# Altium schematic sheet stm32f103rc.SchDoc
size A4
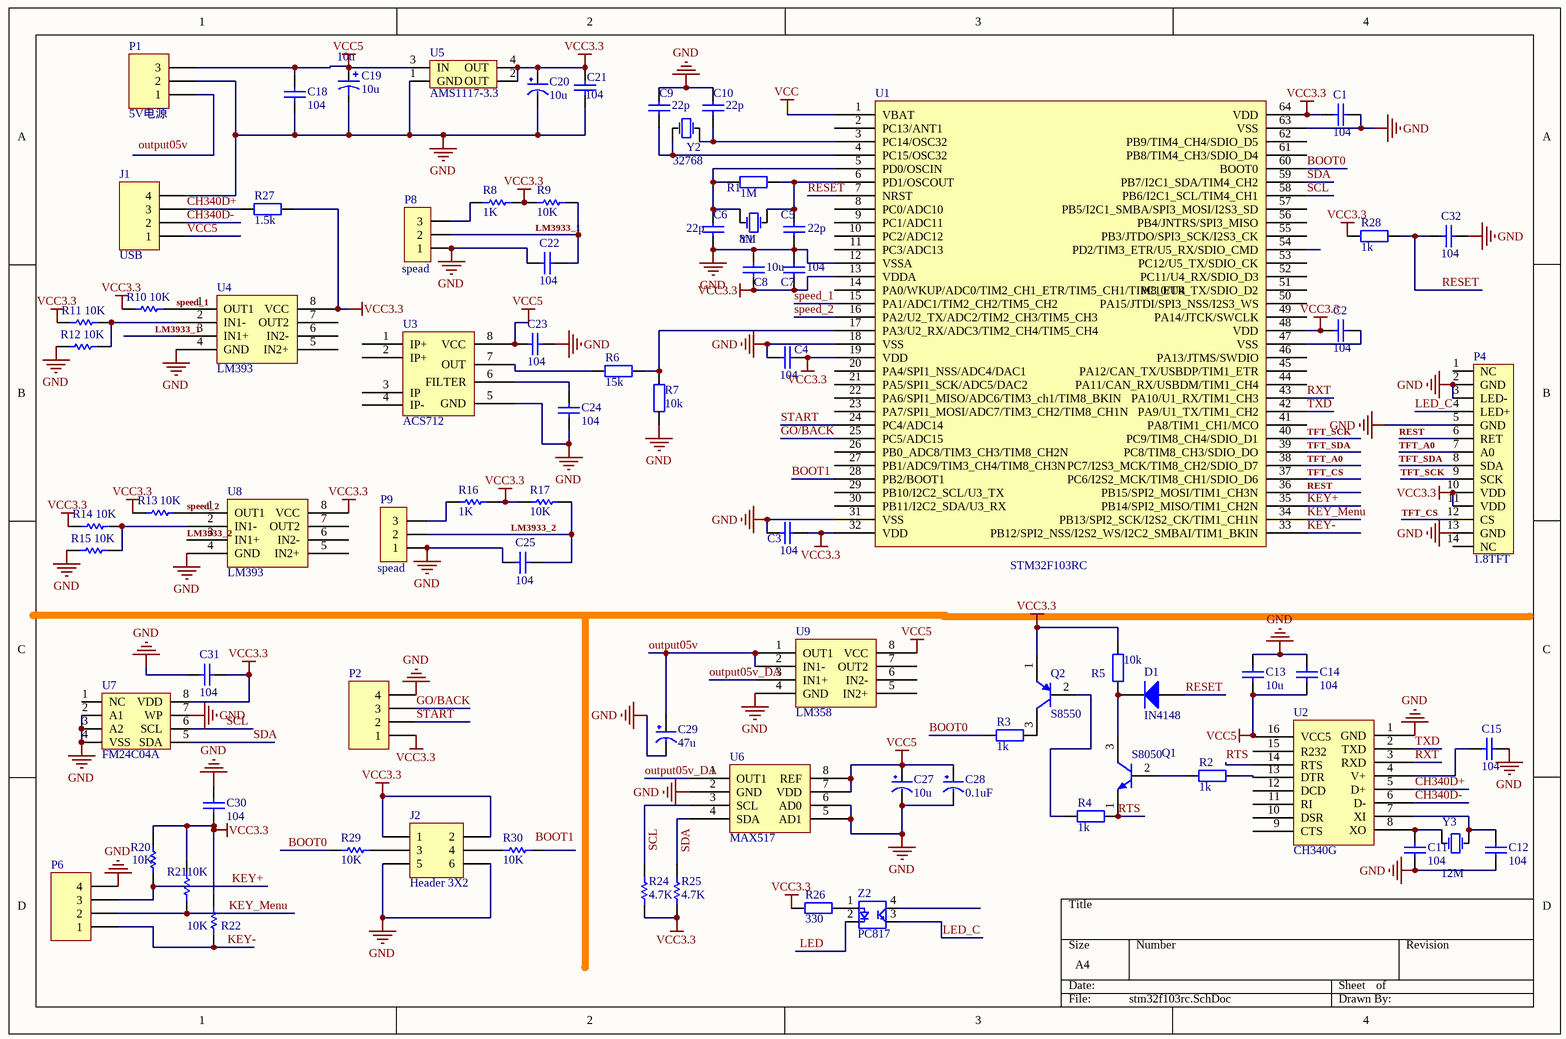
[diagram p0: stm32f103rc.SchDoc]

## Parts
C1  value 104  [0603]  (hidden comment: Cap)
C2  value 104  [0603]  (hidden comment: Cap)
C3  value 104  [0603]  (hidden comment: Cap)
C4  value 104  [0603]  (hidden comment: Cap)
C5  value 22p  [0603]  (hidden comment: Cap)
C6  value 22p  [0603]  (hidden comment: Cap)
C7  value 104  [0603]  (hidden comment: Cap)
C8  value 10u  [1206_C]  (hidden comment: Cap)
C9  value 22p  [0603]  (hidden comment: Cap)
C10  value 22p  [0603]  (hidden comment: Cap)
C11  value 104  [0603]  (hidden comment: Cap)
C12  value 104  [0603]  (hidden comment: Cap)
C13  value 10u  [0603]  (hidden comment: Cap)
C14  value 104  [0603]  (hidden comment: Cap)
C15  value 104  [0603]  (hidden comment: Cap)
C18  value 104  [0603]  (hidden comment: Cap)
C19  10u  [3528]
C20  10u  [3528]
C21  value 104  [0603]  (hidden comment: 0.1u)
C22  104  [0603]
C23  value 104  [0603]  (hidden comment: Cap)
C24  value 104  [0603]  (hidden comment: Cap)
C25  104  [0603]
C27  10u  [3528]
C28  0.1uF  [0603]
C29  47u  [1206]
C30  value 104  [C-RAD-0603]  (hidden comment: Cap)
C31  value 104  [C-RAD-0603]  (hidden comment: Cap)
C32  value 104  [0603]  (hidden comment: Cap)
D1  Type: IN4148  [DIODE-1206]  (hidden comment: Diode)
J1  USB  [HDR1X4]
J2  Header 3X2  [HDR2X3]
P1  5V电源
P2  霍尔接口  [HEADER4---1.8]  (value not drawn)
P4  1.8TFT  [1.8TFT - duplicate]
P6  霍尔接口  [SIP4]  (value not drawn)
P8  spead  [SIP3]
P9  spead  [HEADER3---1.8]
Q1  S8050  [SOT23]
Q2  S8550  [SOT-23]
R1  value 1M  [0603-1]  (hidden comment: Res1)
R2  value 1k  [0603]  (hidden comment: Res1)
R3  value 1k  [0603]  (hidden comment: Res1)
R4  value 1k  [0603]  (hidden comment: Res1)
R5  value 10k  [0603]  (hidden comment: Res1)
R6  value 15k  [0603]  (hidden comment: Res1)
R7  value 10k  [0603-1]  (hidden comment: Res1)
R8  1K  [0603]
R9  10K  [0603]
R10  10K  [0603]
R11  10K  [0603]
R12  10K  [0603]
R13  10K  [0603]
R14  10K  [0603]
R15  10K  [0603]
R16  1K  [0603]
R17  10K  [0603]
R20  10K  [0603]
R21  10K  [0603]
R22  10K  [0603]
R24  4.7K  [0603]
R25  4.7K  [0603]
R26  330  [0603]
R27  value 1.5k  [0603]  (hidden comment: Res1)
R28  value 1k  [0603]  (hidden comment: Res1)
R29  value 10K  [0603]  (hidden comment: 4.7K)
R30  value 10K  [0603]  (hidden comment: 4.7K)
U1  STM32F103RC  [LQFP-64]
U2  CH340G  [SO-16]
U3  ACS712  [SO-8]
U4  LM393  [SO-8]
U5  AMS1117-3.3  [3.3V]
U6  MAX517  [SO-8]
U7  FM24C04A  [SO-8]
U8  LM393  [SO-8]
U9  LM358  [SO-8]
Y1  value 8M  [X-SM49]  (hidden comment: XTAL)
Y2  value 32768  [X-TC15]  (hidden comment: XTAL)
Y3  value 12M  [X-SM49]  (hidden comment: XTAL)
Z2  PC817  [PC817]

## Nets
GND: C1.2 C3.1 C4.1 C5.1 C6.1 C7.2 C8.1 C9.2 C10.2 C11.1 C12.1 C13.2 C14.2 C15.2 C18.1 C19.2 C20.2(GND) C21.1 C22.1 C23.1 C24.1 C25.1 C27.2(GND) C28.2(GND) C29.2(GND) C30.1 C31.2 C32.2 J1.4 J2.5 J2.6 P1.2 P2.4 P4.2(GND) P4.3(LED-) P4.5(GND) P4.13(GND) P6.4 P8.1 P9.1 R7.2 R12.2 R15.2 U1.12(VSSA) U1.18(VSS) U1.31(VSS) U1.63(VSS) U2.1(GND) U3.5(GND) U4.4(GND) U5.1(GND) U6.2(GND) U6.5(AD1) U6.6(AD0) U7.2(A1) U7.3(A2) U7.4(VSS) U7.7(WP) U8.4(GND) U9.4(GND)
VCC: U1.1(VBAT)
VCC3.3: C1.1 C2.1 C3.2 C4.2 C7.1 C8.2 C20.1(VCC) C21.2 C30.2 C31.1 J2.1 J2.2 P2.1 P4.10(VDD) P4.11(VDD) Q2.1(E) R5.1 R8.2 R9.1 R10.2 R11.2 R13.2 R14.2 R16.2 R17.1 R20.1 R21.2 R22.1 R24.2 R25.2 R26.2 R27.1 R28.1 U1.13(VDDA) U1.19(VDD) U1.32(VDD) U1.48(VDD) U1.64(VDD) U4.8(VCC) U5.2(OUT) U5.4(OUT) U7.8(VDD) U8.8(VCC)
VCC5: C13.1 C14.1 C18.2 C19.1 C23.2 C27.1(VCC) C28.1(VCC) J1.1 P1.3 U2.16(VCC5) U3.8(VCC) U5.3(IN) U6.7(VDD) U6.8(REF) U9.8(VCC)
BOOT0: R3.1 R29.2 U1.60(BOOT0)
BOOT1: U1.28(PB2/BOOT1)
CH340D+: J1.3 R27.2 U2.5(D+)
CH340D-: J1.2 U2.6(D-)
GO/BACK: P2.3 U1.25(PC5/ADC15)
KEY+: P6.3 R20.2 U1.35(PB14/SPI2_MISO/TIM1_CH2N)
KEY-: P6.1 R22.2 U1.33(PB12/SPI2_NSS/I2S2_WS/I2C2_SMBAI/TIM1_BKIN)
KEY_Menu: P6.2 R21.1 U1.34(PB13/SPI2_SCK/I2S2_CK/TIM1_CH1N)
LED: Z2.2
LED_C: P4.4(LED+) Z2.3
LM3933_1: C22.2 P8.2 R9.2 U4.3(IN1+)
LM3933_2: C25.2 P9.2 R17.2 U8.3(IN1+)
output05v: C29.1(VCC) U9.1(OUT1) U9.2(IN1-)
output05v_DA: U6.1(OUT1) U9.3(IN1+)
RESET: C32.1 D1.1(A) R28.2 U1.7(NRST)
REST: P4.6(RET) U1.36(PB15/SPI2_MOSI/TIM1_CH3N)
RTS: Q1.1(E) R4.2 U2.14(RTS)
RXT: U1.43(PA10/U1_RX/TIM1_CH3) U2.3(RXD)
SCL: R24.1 U1.58(PB6/I2C1_SCL/TIM4_CH1) U6.3(SCL) U7.6(SCL)
SDA: R25.1 U1.59(PB7/I2C1_SDA/TIM4_CH2) U6.4(SDA) U7.5(SDA)
speed_1: R10.1 U1.15(PA1/ADC1/TIM2_CH2/TIM5_CH2) U4.1(OUT1)
speed_2: R13.1 U1.16(PA2/U2_TX/ADC2/TIM2_CH3/TIM5_CH3) U8.1(OUT1)
START: P2.2 U1.24(PC4/ADC14)
TFT_A0: P4.7(A0) U1.38(PC7/I2S3_MCK/TIM8_CH2/SDIO_D7)
TFT_CS: P4.12(CS) U1.37(PC6/I2S2_MCK/TIM8_CH1/SDIO_D6)
TFT_SCK: P4.9(SCK) U1.40(PC9/TIM8_CH4/SDIO_D1)
TFT_SDA: P4.8(SDA) U1.39(PC8/TIM8_CH3/SDIO_DO)
TXD: U1.42(PA9/U1_TX/TIM1_CH2) U2.2(TXD)
NetC2_2: C2.2 U1.47(VSS)
NetC5_2: C5.2 R1.2 U1.6(PD1/OSCOUT) Y1.1(OSC1)
NetC6_2: C6.2 R1.1 U1.5(PD0/OSCIN) Y1.2(OSC2)
NetC9_1: C9.1 U1.4(PC15/OSC32) Y2.1(OSC1)
NetC10_1: C10.1 U1.3(PC14/OSC32) Y2.2(OSC2)
NetC11_2: C11.2 U2.8(XO) Y3.2(OSC2)
NetC12_2: C12.2 U2.7(XI) Y3.1(OSC1)
NetC15_1: C15.1 U2.4(V+)
NetC24_2: C24.2 U3.6(FILTER)
NetD1_2: D1.2(K) Q1.3(C) R5.2
NetJ2_3: J2.3 R29.1
NetJ2_4: J2.4 R30.2
NetP8_3: P8.3 R8.2
NetP9_3: P9.3 R16.2
NetQ1_2: Q1.2(B) R2.1
NetQ2_2: Q2.2(B) R4.1
NetQ2_3: Q2.3(C) R3.2
NetR2_2: R2.2 U2.13(DTR)
NetR6_1: R6.1 U3.7(OUT)
NetR6_2: R6.2 R7.1 U1.17(PA3/U2_RX/ADC3/TIM2_CH4/TIM5_CH4)
NetR11_1: R11.1 R12.1 U4.2(IN1-)
NetR14_1: R14.1 R15.1 U8.2(IN1-)
NetR26_1: R26.1 Z2.1

Not connected (* = marked no-connect by the designer): P1 1; P4 1(NC) 14(NC); R30 1; U1 2(PC13/ANT1) 8(PC0/ADC10) 9(PC1/ADC11) 10(PC2/ADC12) 11(PC3/ADC13) 14(PA0/WKUP/ADC0/TIM2_CH1_ETR/TIM5_CH1/TIM8_ETR) 20(PA4/SPI1_NSS/ADC4/DAC1) 21(PA5/SPI1_SCK/ADC5/DAC2) 22(PA6/SPI1_MISO/ADC6/TIM3_ch1/TIM8_BKIN) 23(PA7/SPI1_MOSI/ADC7/TIM3_CH2/TIM8_CH1N) 26(PB0_ADC8/TIM3_CH3/TIM8_CH2N) 27(PB1/ADC9/TIM3_CH4/TIM8_CH3N) 29(PB10/I2C2_SCL/U3_TX) 30(PB11/I2C2_SDA/U3_RX) 41(PA8/TIM1_CH1/MCO) 44(PA11/CAN_RX/USBDM/TIM1_CH4) 45(PA12/CAN_TX/USBDP/TIM1_ETR) 46(PA13/JTMS/SWDIO) 49(PA14/JTCK/SWCLK) 50(PA15/JTDI/SPI3_NSS/I2S3_WS) 51(PC10/U4_TX/SDIO_D2) 52(PC11/U4_RX/SDIO_D3) 53(PC12/U5_TX/SDIO_CK) 54(PD2/TIM3_ETR/U5_RX/SDIO_CMD) 55(PB3/JTDO/SPI3_SCK/I2S3_CK) 56(PB4/JNTRS/SPI3_MISO) 57(PB5/I2C1_SMBA/SPI3_MOSI/I2S3_SD) 61(PB8/TIM4_CH3/SDIO_D4) 62(PB9/TIM4_CH4/SDIO_D5); U2 9(CTS) 10(DSR) 11(RI) 12(DCD) 15(R232); U3 1(IP+) 2(IP+) 3(IP) 4(IP-); U4 5(IN2+) 6(IN2-) 7(OUT2); U7 1(NC); U8 5(IN2+) 6(IN2-) 7(OUT2); U9 5(IN2+) 6(IN2-) 7(OUT2); Z2 4

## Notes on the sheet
- Labels drawn without touching a wire or pin: BOOT1, output05v

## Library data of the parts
C1-C15 C18 C23 C24 C30-C32 = Cap: 无极性电容
C19 = CAP+
C20 C27-C29 = CAP
C21 C22 C25 = Cap: Capacitor
D1 = Diode: 二极管
J1 P2 P6 = Header 4: Header, 4-Pin
J2 = Header 3X2: Header, 3-Pin, Dual row
P1 = Header 3: Header, 3-Pin
P8 P9 = CON3
Q1 = S8050: NPN三极管
Q2 = S8550: PNP三极管
R1-R7 R27 R28 = Res1: 贴片电阻
R8-R17 R20-R22 R24 R25 R29 R30 = Res Semi: Semiconductor Resistor
R26 = Res2: Resistor; Value: 4K7
U4 U8 = LM358
U5 = AMS1117
Y1-Y3 = XTAL: 晶振
Z2 = TLP521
